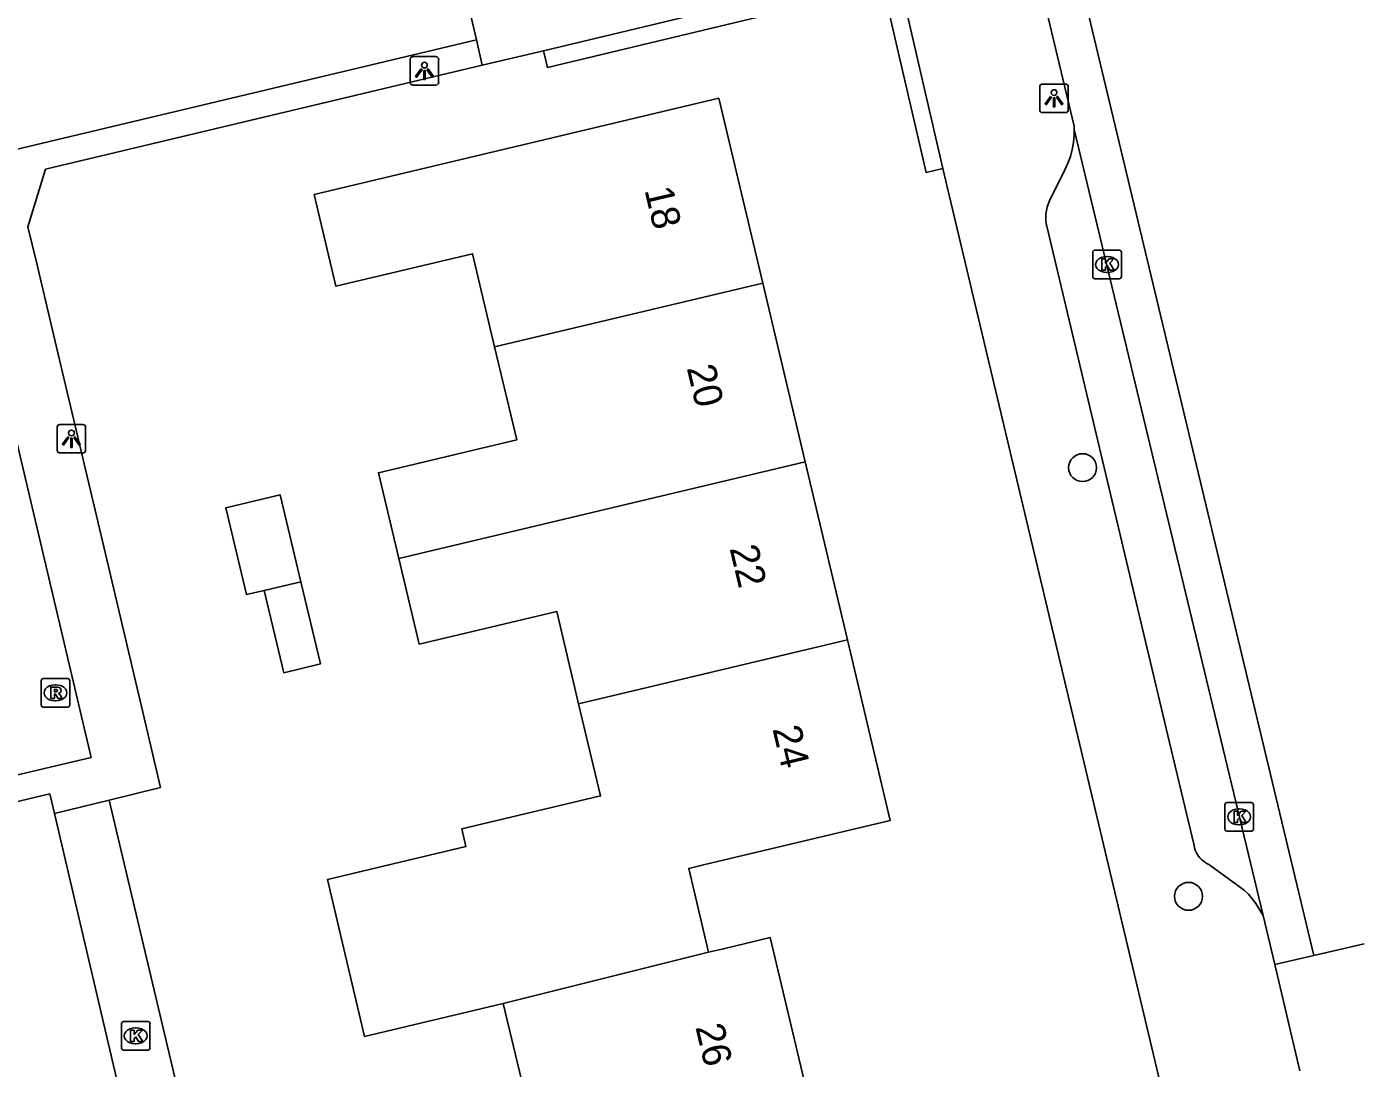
# Model space of a CAD drawing. Extents: x 157663 to 158496, y 379212 to 380934.
# Drawn here: x 158320.09 to 158366.94, y 380832.57 to 380869.04 of the extents above; entities that cross this region are included whole.
import ezdxf

# ---------------------------------------------------------------- set-up
doc = ezdxf.new("R2010")
doc.units = 0
for name, color, linetype in [('IMGEO_Boom', 7, 'Continuous'), ('IMGEO_Haag', 7, 'Continuous'), ('IMGEO_Hek', 7, 'Continuous'), ('IMGEO_Kolk', 7, 'Continuous'), ('IMGEO_Lichtpunt', 7, 'Continuous'), ('IMGEO_Pand', 7, 'Continuous'), ('IMGEO_Pand_nummerreeks', 7, 'Continuous'), ('IMGEO_Rijbaan_lokaal_gesloten', 7, 'Continuous'), ('IMGEO_Rijbaan_lokaal_open', 7, 'Continuous'), ('IMGEO_Rioolput', 7, 'Continuous'), ('IMGEO_Voetpad_open', 7, 'Continuous')]:
    doc.layers.add(name, color=color, linetype=linetype)

msp = doc.modelspace()

# ---------------------------------------------------------------- linework, layer by layer
at = {"layer": 'IMGEO_Boom'}
for centre in [(158357.074, 380853.601), (158360.786, 380838.588)]:
    msp.add_circle(centre, 0.489, dxfattribs=at)
at = {"layer": 'IMGEO_Haag'}
msp.add_lwpolyline([(158352.177, 380864.073), (158351.592, 380863.938), (158350.092, 380870.437), (158338.328, 380867.618), (158338.188, 380868.201)], dxfattribs=at)
at = {"layer": 'IMGEO_Hek'}
for points in [[(158335.303, 380867.521), (158320.751, 380864.05), (158320.132, 380862.029), (158320.425, 380860.796)], [(158320.425, 380860.796), (158321.132, 380857.819)], [(158321.132, 380857.819), (158322.701, 380851.22)], [(158322.701, 380851.22), (158324.11, 380845.231)], [(158322.972, 380841.959), (158324.771, 380842.402), (158324.11, 380845.231)], [(158337.257, 380811.425), (158330.575, 380809.862), (158322.972, 380841.959)]]:
    msp.add_lwpolyline(points, dxfattribs=at)
at = {"layer": 'IMGEO_Kolk'}
for p, q in [((158357.432, 380860.292), (158357.432, 380861.144)), ((158357.507, 380861.218), (158358.359, 380861.218)), ((158357.92, 380860.998), (158357.945, 380860.998)), ((158358.433, 380861.144), (158358.433, 380860.292)), ((158358.359, 380860.218), (158357.507, 380860.218)), ((158357.943, 380860.438), (158357.918, 380860.438)), ((158362.06, 380840.945), (158362.06, 380841.797)), ((158362.135, 380841.871), (158362.987, 380841.871)), ((158363.061, 380841.797), (158363.061, 380840.945)), ((158362.548, 380841.651), (158362.573, 380841.651)), ((158362.987, 380840.871), (158362.135, 380840.871)), ((158362.571, 380841.091), (158362.546, 380841.091)), ((158323.405, 380833.275), (158323.405, 380834.127)), ((158323.48, 380834.201), (158324.332, 380834.201)), ((158323.893, 380833.981), (158323.918, 380833.981)), ((158324.406, 380834.127), (158324.406, 380833.275)), ((158323.916, 380833.421), (158323.891, 380833.421)), ((158324.332, 380833.201), (158323.48, 380833.201))]:
    msp.add_line(p, q, dxfattribs=at)
for points in [[(158357.432, 380860.292), (158357.432, 380861.144)], [(158357.507, 380861.218), (158358.359, 380861.218)], [(158358.433, 380861.144), (158358.433, 380860.292)], [(158357.753, 380860.918), (158357.876, 380860.918), (158357.876, 380860.767), (158358.006, 380860.918), (158358.17, 380860.918), (158358.024, 380860.767), (158358.177, 380860.518), (158358.025, 380860.518), (158357.94, 380860.682), (158357.876, 380860.615), (158357.876, 380860.518), (158357.753, 380860.518), (158357.753, 380860.918)], [(158358.359, 380860.218), (158357.507, 380860.218)], [(158362.06, 380840.945), (158362.06, 380841.797)], [(158362.135, 380841.871), (158362.987, 380841.871)], [(158363.061, 380841.797), (158363.061, 380840.945)], [(158362.381, 380841.571), (158362.504, 380841.571), (158362.504, 380841.42), (158362.634, 380841.571), (158362.798, 380841.571), (158362.652, 380841.42), (158362.805, 380841.171), (158362.653, 380841.171), (158362.568, 380841.335), (158362.504, 380841.268), (158362.504, 380841.171), (158362.381, 380841.171), (158362.381, 380841.571)], [(158362.987, 380840.871), (158362.135, 380840.871)], [(158323.405, 380833.275), (158323.405, 380834.127)], [(158323.48, 380834.201), (158324.332, 380834.201)], [(158323.726, 380833.901), (158323.849, 380833.901), (158323.849, 380833.75), (158323.979, 380833.901), (158324.143, 380833.901), (158323.997, 380833.75), (158324.15, 380833.501), (158323.998, 380833.501), (158323.913, 380833.665), (158323.849, 380833.598), (158323.849, 380833.501), (158323.726, 380833.501), (158323.726, 380833.901)], [(158324.406, 380834.127), (158324.406, 380833.275)], [(158324.332, 380833.201), (158323.48, 380833.201)]]:
    msp.add_lwpolyline(points, dxfattribs=at)
for centre, start, end in [((158357.509, 380861.142), 91.552, 178.448), ((158357.509, 380861.142), 91.552, 178.448), ((158358.357, 380861.142), 1.552, 88.448), ((158358.357, 380861.142), 1.552, 88.448), ((158357.509, 380860.294), 181.552, 268.448), ((158357.509, 380860.294), 181.552, 268.448), ((158358.357, 380860.294), 271.552, 358.448), ((158358.357, 380860.294), 271.552, 358.448), ((158362.137, 380841.795), 91.552, 178.448), ((158362.137, 380841.795), 91.552, 178.448), ((158362.985, 380841.795), 1.552, 88.448), ((158362.985, 380841.795), 1.552, 88.448), ((158362.137, 380840.947), 181.552, 268.448), ((158362.137, 380840.947), 181.552, 268.448), ((158362.985, 380840.947), 271.552, 358.448), ((158362.985, 380840.947), 271.552, 358.448), ((158323.482, 380834.125), 91.552, 178.448), ((158323.482, 380834.125), 91.552, 178.448), ((158324.33, 380834.125), 1.552, 88.448), ((158324.33, 380834.125), 1.552, 88.448), ((158323.482, 380833.277), 181.552, 268.448), ((158323.482, 380833.277), 181.552, 268.448), ((158324.33, 380833.277), 271.552, 358.448), ((158324.33, 380833.277), 271.552, 358.448)]:
    msp.add_arc(centre, 0.0765, start, end, dxfattribs=at)
for centre, major_axis, ratio, start_param, end_param in [((158357.919, 380860.718), (-0.387, 0.002), 0.722429, 4.712389, 7.853982), ((158357.944, 380860.718), (-0.39, 0.002), 0.717154, 1.570796, 4.712389), ((158362.547, 380841.371), (-0.387, 0.002), 0.722429, 4.712389, 7.853982), ((158362.572, 380841.371), (-0.39, 0.002), 0.717154, 1.570796, 4.712389), ((158323.892, 380833.701), (-0.387, 0.002), 0.722429, 4.712389, 7.853982), ((158323.917, 380833.701), (-0.39, 0.002), 0.717154, 1.570796, 4.712389)]:
    msp.add_ellipse(centre, major_axis=major_axis, ratio=ratio, start_param=start_param, end_param=end_param, dxfattribs=at)
at = {"layer": 'IMGEO_Lichtpunt'}
for p, q in [((158334.424, 380867.993), (158333.616, 380867.993)), ((158334.424, 380867.993), (158333.616, 380867.993)), ((158333.522, 380867.898), (158333.522, 380867.091)), ((158333.522, 380867.898), (158333.522, 380867.091)), ((158334.518, 380867.091), (158334.518, 380867.898)), ((158334.518, 380867.091), (158334.518, 380867.898)), ((158356.478, 380867.032), (158355.67, 380867.032)), ((158356.478, 380867.032), (158355.67, 380867.032)), ((158333.616, 380866.997), (158334.424, 380866.997)), ((158333.616, 380866.997), (158334.424, 380866.997)), ((158355.576, 380866.937), (158355.576, 380866.13)), ((158355.576, 380866.937), (158355.576, 380866.13)), ((158356.572, 380866.13), (158356.572, 380866.937)), ((158356.572, 380866.13), (158356.572, 380866.937)), ((158355.67, 380866.036), (158356.478, 380866.036)), ((158355.67, 380866.036), (158356.478, 380866.036)), ((158321.154, 380855.016), (158321.154, 380854.209)), ((158321.154, 380855.016), (158321.154, 380854.209)), ((158322.056, 380855.111), (158321.248, 380855.111)), ((158322.056, 380855.111), (158321.248, 380855.111)), ((158322.15, 380854.209), (158322.15, 380855.016)), ((158322.15, 380854.209), (158322.15, 380855.016)), ((158321.248, 380854.115), (158322.056, 380854.115)), ((158321.248, 380854.115), (158322.056, 380854.115))]:
    msp.add_line(p, q, dxfattribs=at)
for points in [[(158333.896, 380867.562), (158333.935, 380867.534), (158333.747, 380867.272), (158333.709, 380867.299), (158333.896, 380867.562)], [(158333.998, 380867.514), (158334.045, 380867.514), (158334.045, 380867.192), (158333.998, 380867.192), (158333.998, 380867.514)], [(158334.108, 380867.534), (158334.146, 380867.561), (158334.333, 380867.299), (158334.294, 380867.271), (158334.108, 380867.534)], [(158355.95, 380866.601), (158355.989, 380866.573), (158355.801, 380866.311), (158355.763, 380866.338), (158355.95, 380866.601)], [(158356.052, 380866.553), (158356.099, 380866.553), (158356.099, 380866.231), (158356.052, 380866.231), (158356.052, 380866.553)], [(158356.162, 380866.573), (158356.2, 380866.6), (158356.387, 380866.338), (158356.348, 380866.31), (158356.162, 380866.573)], [(158321.528, 380854.68), (158321.567, 380854.652), (158321.379, 380854.39), (158321.341, 380854.417), (158321.528, 380854.68)], [(158321.63, 380854.632), (158321.677, 380854.632), (158321.677, 380854.31), (158321.63, 380854.31), (158321.63, 380854.632)], [(158321.74, 380854.652), (158321.778, 380854.679), (158321.965, 380854.417), (158321.926, 380854.389), (158321.74, 380854.652)]]:
    msp.add_lwpolyline(points, dxfattribs=at)
for centre in [(158334.021, 380867.696), (158356.075, 380866.735), (158321.653, 380854.814)]:
    msp.add_circle(centre, 0.0994, dxfattribs=at)
for centre, start, end in [((158333.616, 380867.898), 90, 180), ((158333.616, 380867.898), 90, 180), ((158334.424, 380867.898), 0, 90), ((158334.424, 380867.898), 0, 90), ((158333.616, 380867.091), 180, 270), ((158333.616, 380867.091), 180, 270), ((158334.424, 380867.091), 270, 0), ((158334.424, 380867.091), 270, 360), ((158355.67, 380866.937), 90, 180), ((158355.67, 380866.937), 90, 180), ((158356.478, 380866.937), 0, 90), ((158356.478, 380866.937), 0, 90), ((158355.67, 380866.13), 180, 270), ((158355.67, 380866.13), 180, 270), ((158356.478, 380866.13), 270, 0), ((158356.478, 380866.13), 270, 360), ((158321.248, 380855.016), 90, 180), ((158321.248, 380855.016), 90, 180), ((158322.056, 380855.016), 0, 90), ((158322.056, 380855.016), 0, 90), ((158321.248, 380854.209), 180, 270), ((158321.248, 380854.209), 180, 270), ((158322.056, 380854.209), 270, 0), ((158322.056, 380854.209), 270, 360)]:
    msp.add_arc(centre, 0.0946, start, end, dxfattribs=at)
at = {"layer": 'IMGEO_Pand'}
for points in [[(158336.48, 380857.832), (158335.705, 380861.091), (158330.92, 380859.954), (158330.157, 380863.165), (158344.332, 380866.534), (158345.869, 380860.063)], [(158336.48, 380857.832), (158345.869, 380860.063)], [(158345.869, 380860.063), (158347.357, 380853.803)], [(158333.122, 380850.42), (158332.408, 380853.422), (158337.254, 380854.573), (158336.48, 380857.832)], [(158333.122, 380850.42), (158347.357, 380853.803)], [(158347.357, 380853.803), (158348.837, 380847.572)], [(158329.689, 380849.604), (158328.962, 380852.651), (158327.062, 380852.198), (158327.789, 380849.153), (158328.402, 380849.298)], [(158339.421, 380845.335), (158338.653, 380848.567), (158333.834, 380847.422), (158333.122, 380850.42)], [(158328.402, 380849.298), (158329.689, 380849.604)], [(158329.689, 380849.604), (158330.376, 380846.726), (158329.089, 380846.419), (158328.402, 380849.298)], [(158348.837, 380847.572), (158339.421, 380845.335)], [(158348.837, 380847.572), (158350.34, 380841.247), (158343.793, 380839.691), (158343.277, 380839.568), (158343.976, 380836.629)], [(158336.781, 380834.836), (158331.925, 380833.682), (158330.619, 380839.175), (158335.475, 380840.329), (158335.328, 380840.948), (158340.189, 380842.103), (158339.421, 380845.335)], [(158343.976, 380836.629), (158344.492, 380836.752), (158346.135, 380837.142), (158347.662, 380830.717)], [(158343.976, 380836.629), (158336.781, 380834.836)], [(158333.071, 380828.856), (158332.71, 380830.377), (158337.566, 380831.531), (158336.781, 380834.836)]]:
    msp.add_lwpolyline(points, dxfattribs=at)
at = {"layer": 'IMGEO_Rijbaan_lokaal_gesloten'}
for points in [[(158344.843, 380907.239), (158348.766, 380898.748), (158351.636, 380891.16), (158355.633, 380876.355), (158365.174, 380836.518)], [(158356.781, 380865.443), (158356.775, 380865.562), (158354.277, 380876.007)], [(158356.781, 380865.443), (158363.399, 380837.913)], [(158363.81, 380836.205), (158363.399, 380837.913)]]:
    msp.add_lwpolyline(points, dxfattribs=at)
at = {"layer": 'IMGEO_Rijbaan_lokaal_open'}
for points in [[(158335.368, 380870.628), (158335.841, 380868.585)], [(158335.841, 380868.585), (158317.438, 380864.207), (158322.34, 380843.453), (158256.423, 380827.895), (158256.672, 380826.915)], [(158365.174, 380836.518), (158366.942, 380836.924)], [(158365.174, 380836.518), (158363.81, 380836.205)], [(158363.81, 380836.205), (158364.691, 380832.473)]]:
    msp.add_lwpolyline(points, dxfattribs=at)
at = {"layer": 'IMGEO_Rioolput'}
for p, q in [((158320.594, 380845.287), (158320.594, 380846.139)), ((158320.669, 380846.213), (158321.521, 380846.213)), ((158321.082, 380845.993), (158321.107, 380845.993)), ((158321.595, 380846.139), (158321.595, 380845.287)), ((158321.521, 380845.213), (158320.669, 380845.213)), ((158321.105, 380845.433), (158321.08, 380845.433))]:
    msp.add_line(p, q, dxfattribs=at)
for points in [[(158320.594, 380845.287), (158320.594, 380846.139)], [(158320.669, 380846.213), (158321.521, 380846.213)], [(158321.595, 380846.139), (158321.595, 380845.287)], [(158321.183, 380845.911), (158320.931, 380845.913), (158320.931, 380845.513)], [(158320.931, 380845.513), (158321.055, 380845.513), (158321.055, 380845.675), (158321.066, 380845.675)], [(158321.109, 380845.832), (158321.055, 380845.832), (158321.055, 380845.751)], [(158321.055, 380845.751), (158321.107, 380845.751)], [(158321.113, 380845.646), (158321.184, 380845.513), (158321.324, 380845.513), (158321.259, 380845.639)], [(158321.521, 380845.213), (158320.669, 380845.213)]]:
    msp.add_lwpolyline(points, dxfattribs=at)
for centre, radius, start, end in [((158320.671, 380846.137), 0.0765, 91.552, 178.448), ((158320.671, 380846.137), 0.0765, 91.552, 178.448), ((158321.519, 380846.137), 0.0765, 1.552, 88.448), ((158321.519, 380846.137), 0.0765, 1.552, 88.448), ((158321.065, 380845.622), 0.0533, 26.0293, 88.6989), ((158321.091, 380845.94), 0.19, 274.7715, 282.9687), ((158321.115, 380845.736), 0.0964, 77.0061, 93.1865), ((158321.129, 380845.793), 0.0378, 276.6634, 79.6772), ((158321.182, 380845.801), 0.109, 350.3612, 89.416), ((158321.18, 380845.801), 0.112, 277.5842, 350.9817), ((158321.164, 380845.586), 0.108, 29.5134, 73.7905), ((158320.671, 380845.289), 0.0765, 181.552, 268.448), ((158320.671, 380845.289), 0.0765, 181.552, 268.448), ((158321.519, 380845.289), 0.0765, 271.552, 358.448), ((158321.519, 380845.289), 0.0765, 271.552, 358.448)]:
    msp.add_arc(centre, radius, start, end, dxfattribs=at)
for centre, major_axis, ratio, start_param, end_param in [((158321.081, 380845.713), (-0.387, 0.002), 0.722429, 4.712389, 7.853982), ((158321.106, 380845.713), (-0.39, 0.002), 0.717154, 1.570796, 4.712389)]:
    msp.add_ellipse(centre, major_axis=major_axis, ratio=ratio, start_param=start_param, end_param=end_param, dxfattribs=at)
at = {"layer": 'IMGEO_Voetpad_open'}
for points in [[(158352.177, 380864.073), (158350.54, 380871.161), (158338.188, 380868.201)], [(158335.841, 380868.585), (158336.047, 380867.696)], [(158338.188, 380868.201), (158336.047, 380867.696)], [(158336.047, 380867.696), (158335.303, 380867.521), (158320.751, 380864.05), (158320.132, 380862.029), (158320.425, 380860.796), (158321.132, 380857.819), (158322.701, 380851.22), (158324.11, 380845.231), (158324.771, 380842.402), (158322.972, 380841.959)], [(158363.399, 380837.913), (158363.141, 380838.339), (158363.02, 380838.505), (158362.884, 380838.659), (158362.736, 380838.8), (158362.609, 380838.902), (158361.537, 380839.685), (158361.497, 380839.702), (158361.426, 380839.737), (158361.359, 380839.779), (158361.296, 380839.826), (158361.237, 380839.879), (158361.183, 380839.937), (158361.134, 380840), (158361.091, 380840.066), (158361.055, 380840.137), (158361.024, 380840.21), (158361.001, 380840.286), (158360.984, 380840.363), (158360.125, 380843.972), (158355.822, 380862.055), (158355.805, 380862.135), (158355.79, 380862.252), (158355.785, 380862.37), (158355.791, 380862.489), (158355.807, 380862.606), (158355.834, 380862.721), (158355.871, 380862.833), (158355.918, 380862.942), (158356.449, 380864.03), (158356.558, 380864.259), (158356.646, 380864.496), (158356.713, 380864.741), (158356.758, 380864.991), (158356.78, 380865.243), (158356.781, 380865.443)], [(158363.215, 380817.667), (158352.177, 380864.073)], [(158321.058, 380841.488), (158320.897, 380842.175), (158312.07, 380840.074), (158256.672, 380826.915)], [(158321.058, 380841.488), (158322.972, 380841.959)], [(158322.972, 380841.959), (158330.575, 380809.862), (158337.257, 380811.425)], [(158278.284, 380798.647), (158313.745, 380806.99), (158314.304, 380804.661), (158329, 380808.131), (158323.379, 380831.566), (158321.058, 380841.488)]]:
    msp.add_lwpolyline(points, dxfattribs=at)

# ---------------------------------------------------------------- texts
at = {"layer": 'IMGEO_Pand_nummerreeks'}
for s, rotation, p in [('18', 283.3652, (158341.723, 380863.327)), ('20', 283.3652, (158343.204, 380857.094)), ('22', 283.3652, (158344.705, 380850.778)), ('24', 283.3652, (158346.207, 380844.454)), ('26', 283.3669, (158343.507, 380834.013))]:
    msp.add_text(s, height=1, rotation=rotation, dxfattribs=at).set_placement(p)

doc.saveas('drawing.dxf')
